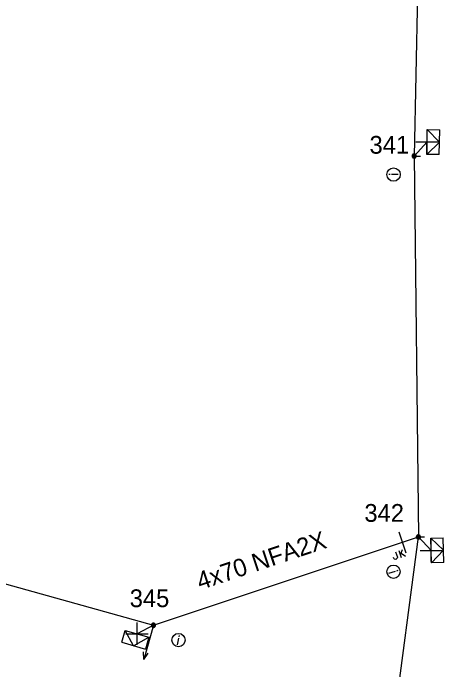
# Model space of a CAD drawing. Extents: x -540466 to -537383, y -1184038 to -1179972.
# Drawn here: x -538053.92 to -538029.65, y -1180842.47 to -1180805.49 of the extents above; entities that cross this region are included whole.
import ezdxf

# ---------------------------------------------------------------- set-up
doc = ezdxf.new("R2010")
doc.units = 0
for name, color, linetype in [('Vrstva 1', 7, 'Continuous'), ('Vrstva 10', 7, 'Continuous'), ('Vrstva 13', 7, 'Continuous'), ('Vrstva 14', 7, 'Continuous'), ('Vrstva 15', 7, 'Continuous'), ('Vrstva 18', 7, 'Continuous'), ('Vrstva 2', 7, 'Continuous'), ('Vrstva 31', 7, 'Continuous'), ('Vrstva 34', 7, 'Continuous'), ('Vrstva 36', 7, 'Continuous'), ('Vrstva 50', 7, 'Continuous'), ('Vrstva 51', 7, 'Continuous'), ('Vrstva 8', 7, 'Continuous'), ('Vrstva 9', 7, 'Continuous')]:
    doc.layers.add(name, color=color, linetype=linetype)

# ---------------------------------------------------------------- blocks, each defined once
blk = doc.blocks.new('NN560')
at = {"layer": 'Vrstva 2'}
for points in [[(1.999, -0.001), (1.59, 0.141)], [(0, -0.001), (1.999, -0.001)], [(1.999, -0.001), (1.59, -0.134)]]:
    blk.add_lwpolyline(points, dxfattribs=at)
blk = doc.blocks.new('NN840')
at = {"layer": 'Vrstva 15'}
for points in [[(0.003, 0.619), (0.003, -0.631)], [(-0.745, -0.71), (-0.745, -0.66)], [(-0.73, -0.764), (-0.745, -0.71)], [(-0.538, -0.71), (-0.558, -0.764)], [(-0.538, -0.385), (-0.538, -0.71)], [(-0.332, -0.385), (-0.332, -0.798)], [(-0.332, -0.641), (-0.125, -0.385)], [(-0.263, -0.557), (-0.091, -0.798)], [(-0.657, -0.798), (-0.73, -0.764)], [(-0.627, -0.798), (-0.657, -0.798)], [(-0.558, -0.764), (-0.627, -0.798)]]:
    blk.add_lwpolyline(points, dxfattribs=at)
blk = doc.blocks.new('NN770')
at = {"layer": 'Vrstva 10'}
for p, q in [((0.002, 0.187), (0.002, 0.263)), ((0.002, -0.276), (0.002, 0.111))]:
    blk.add_line(p, q, dxfattribs=at)
blk.add_circle((0, -0.008), 0.375, dxfattribs=at)
blk = doc.blocks.new('NN800')
at = {"layer": 'Vrstva 1'}
for points in [[(-0.442, 0.442), (0.442, -0.442)], [(-0.442, -0.442), (0.442, 0.442)]]:
    blk.add_lwpolyline(points, dxfattribs=at)
blk = doc.blocks.new('NN630')
at = {"layer": 'Vrstva 9'}
for points in [[(-0.003, -0.7), (-0.703, 0)], [(-0.703, -0.7), (-0.703, 0), (0.697, 0), (0.697, -0.7)], [(-0.003, -0.7), (0.697, 0)], [(-0.703, -0.7), (0.697, -0.7)]]:
    blk.add_lwpolyline(points, dxfattribs=at)
blk = doc.blocks.new('NN500')
at = {"layer": 'Vrstva 2'}
for points in [[(-0.001, -0.235), (0.023, -0.234), (0.048, -0.23), (0.071, -0.224), (0.094, -0.215), (0.116, -0.204), (0.137, -0.191), (0.156, -0.175), (0.173, -0.158), (0.189, -0.139), (0.202, -0.118), (0.213, -0.096), (0.222, -0.073), (0.229, -0.049), (0.232, -0.025), (0.234, 0), (0.232, 0.024), (0.229, 0.048), (0.222, 0.072), (0.213, 0.095), (0.202, 0.117), (0.189, 0.138), (0.173, 0.157), (0.156, 0.174), (0.137, 0.19), (0.116, 0.203), (0.094, 0.214), (0.071, 0.223), (0.048, 0.229), (0.023, 0.233), (-0.001, 0.235), (-0.026, 0.233), (-0.05, 0.229), (-0.074, 0.223), (-0.097, 0.214), (-0.119, 0.203), (-0.139, 0.19), (-0.158, 0.174), (-0.176, 0.157), (-0.191, 0.138), (-0.205, 0.117), (-0.216, 0.095), (-0.225, 0.072), (-0.231, 0.048), (-0.235, 0.024), (-0.236, 0), (-0.235, -0.025), (-0.231, -0.049), (-0.225, -0.073), (-0.216, -0.096), (-0.205, -0.118), (-0.191, -0.139), (-0.176, -0.158), (-0.158, -0.175), (-0.139, -0.191), (-0.119, -0.204), (-0.097, -0.215), (-0.074, -0.224), (-0.05, -0.23), (-0.026, -0.234), (-0.001, -0.235)], [(-0.001, -0.235), (0.023, -0.234), (0.048, -0.23), (0.071, -0.224), (0.094, -0.215), (0.116, -0.204), (0.137, -0.191), (0.156, -0.175), (0.173, -0.158), (0.189, -0.139), (0.202, -0.118), (0.213, -0.096), (0.222, -0.073), (0.229, -0.049), (0.232, -0.025), (0.234, 0), (0.232, 0.024), (0.229, 0.048), (0.222, 0.072), (0.213, 0.095), (0.202, 0.117), (0.189, 0.138), (0.173, 0.157), (0.156, 0.174), (0.137, 0.19), (0.116, 0.203), (0.094, 0.214), (0.071, 0.223), (0.048, 0.229), (0.023, 0.233), (-0.001, 0.235), (-0.026, 0.233), (-0.05, 0.229), (-0.074, 0.223), (-0.097, 0.214), (-0.119, 0.203), (-0.139, 0.19), (-0.158, 0.174), (-0.176, 0.157), (-0.191, 0.138), (-0.205, 0.117), (-0.216, 0.095), (-0.225, 0.072), (-0.231, 0.048), (-0.235, 0.024), (-0.236, 0), (-0.235, -0.025), (-0.231, -0.049), (-0.225, -0.073), (-0.216, -0.096), (-0.205, -0.118), (-0.191, -0.139), (-0.176, -0.158), (-0.158, -0.175), (-0.139, -0.191), (-0.119, -0.204), (-0.097, -0.215), (-0.074, -0.224), (-0.05, -0.23), (-0.026, -0.234), (-0.001, -0.235)], [(-0.001, -0.206), (0.02, -0.205), (0.041, -0.201), (0.062, -0.196), (0.082, -0.188), (0.101, -0.178), (0.12, -0.167), (0.136, -0.153), (0.151, -0.138), (0.165, -0.121), (0.177, -0.103), (0.186, -0.084), (0.194, -0.064), (0.2, -0.043), (0.203, -0.022), (0.204, 0), (0.203, 0.021), (0.2, 0.042), (0.194, 0.063), (0.186, 0.083), (0.177, 0.102), (0.165, 0.12), (0.151, 0.137), (0.136, 0.152), (0.12, 0.166), (0.101, 0.177), (0.082, 0.187), (0.062, 0.195), (0.041, 0.2), (0.02, 0.204), (-0.001, 0.205), (-0.023, 0.204), (-0.044, 0.2), (-0.065, 0.195), (-0.085, 0.187), (-0.104, 0.177), (-0.122, 0.166), (-0.139, 0.152), (-0.154, 0.137), (-0.167, 0.12), (-0.179, 0.102), (-0.189, 0.083), (-0.197, 0.063), (-0.202, 0.042), (-0.205, 0.021), (-0.207, 0), (-0.205, -0.022), (-0.202, -0.043), (-0.197, -0.064), (-0.189, -0.084), (-0.179, -0.103), (-0.167, -0.121), (-0.154, -0.138), (-0.139, -0.153), (-0.122, -0.167), (-0.104, -0.178), (-0.085, -0.188), (-0.065, -0.196), (-0.044, -0.201), (-0.023, -0.205), (-0.001, -0.206)], [(-0.001, -0.176), (0.017, -0.175), (0.035, -0.172), (0.053, -0.168), (0.07, -0.161), (0.087, -0.153), (0.102, -0.143), (0.116, -0.131), (0.129, -0.118), (0.141, -0.104), (0.151, -0.088), (0.159, -0.072), (0.166, -0.055), (0.171, -0.037), (0.174, -0.019), (0.175, 0), (0.174, 0.018), (0.171, 0.036), (0.166, 0.054), (0.159, 0.071), (0.151, 0.087), (0.141, 0.103), (0.129, 0.117), (0.116, 0.13), (0.102, 0.142), (0.087, 0.152), (0.07, 0.16), (0.053, 0.167), (0.035, 0.172), (0.017, 0.174), (-0.001, 0.175), (-0.02, 0.174), (-0.038, 0.172), (-0.056, 0.167), (-0.073, 0.16), (-0.089, 0.152), (-0.105, 0.142), (-0.119, 0.13), (-0.132, 0.117), (-0.143, 0.103), (-0.153, 0.087), (-0.162, 0.071), (-0.168, 0.054), (-0.173, 0.036), (-0.176, 0.018), (-0.177, 0), (-0.176, -0.019), (-0.173, -0.037), (-0.168, -0.055), (-0.162, -0.072), (-0.153, -0.088), (-0.143, -0.104), (-0.132, -0.118), (-0.119, -0.131), (-0.105, -0.143), (-0.089, -0.153), (-0.073, -0.161), (-0.056, -0.168), (-0.038, -0.172), (-0.02, -0.175), (-0.001, -0.176)], [(-0.001, -0.147), (0.014, -0.146), (0.029, -0.143), (0.044, -0.139), (0.058, -0.134), (0.072, -0.127), (0.085, -0.119), (0.097, -0.109), (0.107, -0.098), (0.117, -0.086), (0.125, -0.073), (0.132, -0.06), (0.138, -0.046), (0.142, -0.031), (0.144, -0.016), (0.145, 0), (0.144, 0.015), (0.142, 0.03), (0.138, 0.045), (0.132, 0.059), (0.125, 0.073), (0.117, 0.086), (0.107, 0.097), (0.097, 0.108), (0.085, 0.118), (0.072, 0.126), (0.058, 0.133), (0.044, 0.139), (0.029, 0.143), (0.014, 0.145), (-0.001, 0.146), (-0.017, 0.145), (-0.032, 0.143), (-0.046, 0.139), (-0.061, 0.133), (-0.074, 0.126), (-0.087, 0.118), (-0.099, 0.108), (-0.11, 0.097), (-0.119, 0.086), (-0.128, 0.073), (-0.135, 0.059), (-0.14, 0.045), (-0.144, 0.03), (-0.147, 0.015), (-0.147, 0), (-0.147, -0.016), (-0.144, -0.031), (-0.14, -0.046), (-0.135, -0.06), (-0.128, -0.073), (-0.119, -0.086), (-0.11, -0.098), (-0.099, -0.109), (-0.087, -0.119), (-0.074, -0.127), (-0.061, -0.134), (-0.046, -0.139), (-0.032, -0.143), (-0.017, -0.146), (-0.001, -0.147)], [(-0.001, -0.117), (0.011, -0.116), (0.023, -0.114), (0.035, -0.111), (0.046, -0.107), (0.057, -0.101), (0.067, -0.095), (0.077, -0.087), (0.085, -0.078), (0.093, -0.069), (0.1, -0.059), (0.105, -0.048), (0.11, -0.036), (0.113, -0.025), (0.115, -0.013), (0.115, 0), (0.115, 0.012), (0.113, 0.024), (0.11, 0.036), (0.105, 0.047), (0.1, 0.058), (0.093, 0.068), (0.085, 0.078), (0.077, 0.086), (0.067, 0.094), (0.057, 0.101), (0.046, 0.106), (0.035, 0.11), (0.023, 0.114), (0.011, 0.116), (-0.001, 0.116), (-0.013, 0.116), (-0.025, 0.114), (-0.037, 0.11), (-0.049, 0.106), (-0.059, 0.101), (-0.07, 0.094), (-0.079, 0.086), (-0.088, 0.078), (-0.096, 0.068), (-0.102, 0.058), (-0.108, 0.047), (-0.112, 0.036), (-0.115, 0.024), (-0.117, 0.012), (-0.118, 0), (-0.117, -0.013), (-0.115, -0.025), (-0.112, -0.036), (-0.108, -0.048), (-0.102, -0.059), (-0.096, -0.069), (-0.088, -0.078), (-0.079, -0.087), (-0.07, -0.095), (-0.059, -0.101), (-0.049, -0.107), (-0.037, -0.111), (-0.025, -0.114), (-0.013, -0.116), (-0.001, -0.117)], [(-0.001, -0.087), (0.008, -0.087), (0.017, -0.085), (0.026, -0.083), (0.034, -0.08), (0.042, -0.076), (0.05, -0.071), (0.057, -0.065), (0.063, -0.059), (0.069, -0.051), (0.074, -0.044), (0.078, -0.036), (0.081, -0.027), (0.084, -0.019), (0.085, -0.01), (0.086, 0), (0.085, 0.009), (0.084, 0.018), (0.081, 0.026), (0.078, 0.035), (0.074, 0.043), (0.069, 0.051), (0.063, 0.058), (0.057, 0.064), (0.05, 0.07), (0.042, 0.075), (0.034, 0.079), (0.026, 0.082), (0.017, 0.085), (0.008, 0.086), (-0.001, 0.087), (-0.01, 0.086), (-0.019, 0.085), (-0.028, 0.082), (-0.037, 0.079), (-0.045, 0.075), (-0.052, 0.07), (-0.059, 0.064), (-0.066, 0.058), (-0.072, 0.051), (-0.077, 0.043), (-0.081, 0.035), (-0.084, 0.026), (-0.086, 0.018), (-0.088, 0.009), (-0.088, 0), (-0.088, -0.01), (-0.086, -0.019), (-0.084, -0.027), (-0.081, -0.036), (-0.077, -0.044), (-0.072, -0.052), (-0.066, -0.059), (-0.059, -0.065), (-0.052, -0.071), (-0.045, -0.076), (-0.037, -0.08), (-0.028, -0.083), (-0.019, -0.085), (-0.01, -0.087), (-0.001, -0.087)], [(-0.001, -0.058), (0.005, -0.057), (0.011, -0.056), (0.016, -0.055), (0.022, -0.053), (0.027, -0.05), (0.032, -0.047), (0.037, -0.043), (0.041, -0.039), (0.045, -0.034), (0.048, -0.029), (0.051, -0.024), (0.053, -0.018), (0.055, -0.012), (0.056, -0.006), (0.056, 0), (0.056, 0.006), (0.055, 0.011), (0.053, 0.017), (0.051, 0.023), (0.048, 0.028), (0.045, 0.033), (0.041, 0.038), (0.037, 0.042), (0.032, 0.046), (0.027, 0.049), (0.022, 0.052), (0.016, 0.054), (0.011, 0.056), (0.005, 0.057), (-0.001, 0.057), (-0.007, 0.057), (-0.013, 0.056), (-0.019, 0.054), (-0.025, 0.052), (-0.03, 0.049), (-0.035, 0.046), (-0.04, 0.042), (-0.044, 0.038), (-0.048, 0.033), (-0.051, 0.028), (-0.054, 0.023), (-0.056, 0.017), (-0.057, 0.011), (-0.058, 0.006), (-0.059, 0), (-0.058, -0.006), (-0.057, -0.012), (-0.056, -0.018), (-0.054, -0.024), (-0.051, -0.029), (-0.048, -0.034), (-0.044, -0.039), (-0.04, -0.043), (-0.035, -0.047), (-0.03, -0.05), (-0.025, -0.053), (-0.019, -0.055), (-0.013, -0.056), (-0.007, -0.057), (-0.001, -0.058)], [(-0.001, -0.028), (0.002, -0.028), (0.005, -0.028), (0.007, -0.027), (0.01, -0.026), (0.013, -0.024), (0.015, -0.023), (0.017, -0.021), (0.019, -0.019), (0.021, -0.017), (0.023, -0.014), (0.024, -0.012), (0.025, -0.009), (0.026, -0.006), (0.026, -0.003), (0.027, 0), (0.026, 0.002), (0.026, 0.005), (0.025, 0.008), (0.024, 0.011), (0.023, 0.013), (0.021, 0.016), (0.019, 0.018), (0.017, 0.02), (0.015, 0.022), (0.013, 0.024), (0.01, 0.025), (0.007, 0.026), (0.005, 0.027), (0.002, 0.027), (-0.001, 0.027), (-0.004, 0.027), (-0.007, 0.027), (-0.01, 0.026), (-0.012, 0.025), (-0.015, 0.024), (-0.018, 0.022), (-0.02, 0.02), (-0.022, 0.018), (-0.024, 0.016), (-0.025, 0.013), (-0.027, 0.011), (-0.028, 0.008), (-0.028, 0.005), (-0.029, 0.002), (-0.029, 0), (-0.029, -0.003), (-0.028, -0.006), (-0.028, -0.009), (-0.027, -0.012), (-0.025, -0.014), (-0.024, -0.017), (-0.022, -0.019), (-0.02, -0.021), (-0.018, -0.023), (-0.015, -0.024), (-0.012, -0.026), (-0.01, -0.027), (-0.007, -0.028), (-0.004, -0.028), (-0.001, -0.028)], [(0.234, 0), (0.704, 0)]]:
    blk.add_lwpolyline(points, dxfattribs=at)

msp = doc.modelspace()

# ---------------------------------------------------------------- linework, layer by layer
at = {"layer": 'Vrstva 50'}
for points in [[(-538035.202, -1180756.021), (-538035.459, -1180757.579), (-538038.038, -1180773.166), (-538030.938, -1180795.212), (-538031.319, -1180813.535), (-538031.082, -1180834.986)], [(-538075.16, -1180806.08), (-538082.578, -1180816.912), (-538075.193, -1180834.507), (-538066.948, -1180834.145), (-538061.578, -1180835.611), (-538046.012, -1180839.963), (-538031.082, -1180834.986)], [(-538033.892, -1180856.303), (-538031.082, -1180834.986)]]:
    msp.add_lwpolyline(points, dxfattribs=at)
at = {"layer": 'Vrstva 8'}
for points in [[(-538031.319, -1180813.535), (-538030.596, -1180812.738)], [(-538031.082, -1180834.986), (-538030.362, -1180835.746)], [(-538046.012, -1180839.963), (-538046.935, -1180840.437)]]:
    msp.add_lwpolyline(points, dxfattribs=at)

# ---------------------------------------------------------------- block references
at = {"layer": 'Vrstva 13'}
for p, xscale, yscale, rotation in [((-538031.319, -1180813.535), 0.49999999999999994, 0.49999999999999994, -1.2190001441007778), ((-538031.082, -1180834.986), 0.5000000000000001, 0.4999999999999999, 1.2880000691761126), ((-538046.012, -1180839.963), 0.5, 0.5000000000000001, -105.70700002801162)]:
    msp.add_blockref('NN500', p, dxfattribs=dict(at, xscale=xscale, yscale=yscale, rotation=rotation))
at = {"layer": 'Vrstva 13', "rotation": -105.70710278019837}
msp.add_blockref('NN560', (-538046.012, -1180839.963), dxfattribs=at)
at = {"layer": 'Vrstva 18', "rotation": 18.436100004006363}
msp.add_blockref('NN840', (-538031.983, -1180835.286), dxfattribs=at)
at = {"layer": 'Vrstva 31'}
for p, rotation in [((-538030.596, -1180812.738), 88.7811250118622), ((-538030.362, -1180835.746), 91.28781109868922), ((-538046.935, -1180840.437), -15.707102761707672)]:
    msp.add_blockref('NN630', p, dxfattribs=dict(at, rotation=rotation))
at = {"layer": 'Vrstva 34', "rotation": 45}
for p in [(-538030.596, -1180812.738), (-538030.362, -1180835.746), (-538046.935, -1180840.437)]:
    msp.add_blockref('NN800', p, dxfattribs=at)
at = {"layer": 'Vrstva 36'}
for p, rotation in [((-538032.489, -1180814.58), 88.47661388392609), ((-538032.478, -1180836.941), -73.07248609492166), ((-538044.599, -1180840.787), -11.768288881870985)]:
    msp.add_blockref('NN770', p, dxfattribs=dict(at, rotation=rotation))

# ---------------------------------------------------------------- texts
at = {"layer": 'Vrstva 14'}
for s, p in [('341', (-538033.836, -1180813.405)), ('342', (-538034.125, -1180834.135)), ('345', (-538047.349, -1180838.94))]:
    msp.add_text(s, height=1, dxfattribs=at).set_placement(p)
at = {"layer": 'Vrstva 51'}
msp.add_text('4x70 NFA2X', height=1, rotation=18.436, dxfattribs=at).set_placement((-538043.376, -1180837.986))

doc.saveas('drawing.dxf')
